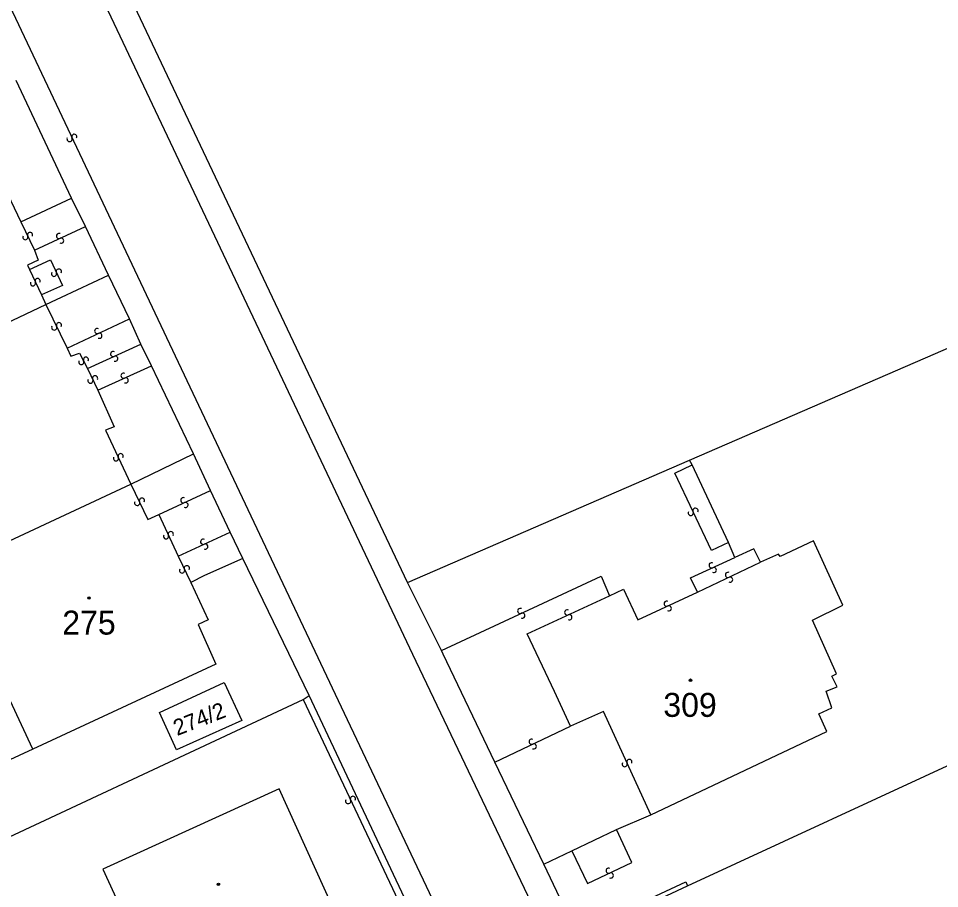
# Model space of a CAD drawing. Extents: x -600391 to -599491, y -1160176 to -1159402.
# Drawn here: x -600122 to -600056.6, y -1159974.1 to -1159912.4 of the extents above; entities that cross this region are included whole.
import ezdxf

# ---------------------------------------------------------------- set-up
doc = ezdxf.new("R2010")
doc.units = 0
for name, color, linetype in [('Level 1', 7, 'Continuous'), ('Level 13', 7, 'Continuous'), ('Level 3', 7, 'Continuous'), ('Level 4', 7, 'Continuous'), ('Level 5', 7, 'Continuous')]:
    doc.layers.add(name, color=color, linetype=linetype)

msp = doc.modelspace()

# ---------------------------------------------------------------- linework, layer by layer
at = {"layer": 'Level 1'}
for points in [[(-600094.36, -1159952.42), (-600122.68, -1159892.59)], [(-600118.2, -1159925.12), (-600122.13, -1159916.77)], [(-600140, -1159926.74), (-600126.12, -1159920.16), (-600124.38, -1159923.72), (-600123.49, -1159923.33), (-600121.81, -1159926.81)], [(-600121.81, -1159926.81), (-600118.2, -1159925.12)], [(-600117.22, -1159927.13), (-600118.2, -1159925.12)], [(-600115.58, -1159930.59), (-600117.22, -1159927.13)], [(-600074.33, -1159943.72), (-600042.25, -1159929.81)], [(-600120.02, -1159932.67), (-600115.58, -1159930.59)], [(-600114.1, -1159933.69), (-600115.58, -1159930.59)], [(-600133.84, -1159939.24), (-600120.02, -1159932.67)], [(-600113.28, -1159935.5), (-600114.1, -1159933.69)], [(-600112.54, -1159937.02), (-600113.28, -1159935.5)], [(-600109.54, -1159943.28), (-600112.54, -1159937.02)], [(-600113.99, -1159945.44), (-600109.54, -1159943.28)], [(-600108.35, -1159945.89), (-600109.54, -1159943.28)], [(-600094.36, -1159952.42), (-600074.33, -1159943.72)], [(-600074.14, -1159944.05), (-600074.33, -1159943.72)], [(-600071.57, -1159949.57), (-600074.14, -1159944.05)], [(-600126.93, -1159951.47), (-600113.99, -1159945.44)], [(-600106.94, -1159948.84), (-600108.35, -1159945.89)], [(-600106.05, -1159950.72), (-600106.94, -1159948.84)], [(-600077.09, -1159968.9), (-600064.59, -1159962.99), (-600065.15, -1159961.74), (-600064.24, -1159961.32), (-600064.64, -1159960.12), (-600063.86, -1159959.81), (-600064.24, -1159959.05), (-600063.9, -1159958.89), (-600065.6, -1159955.09), (-600063.45, -1159954.03), (-600065.53, -1159949.46), (-600067.89, -1159950.56), (-600068.01, -1159950.39), (-600069.3, -1159950.97)], [(-600071.12, -1159950.63), (-600071.57, -1159949.57)], [(-600069.3, -1159950.97), (-600069.76, -1159950.02), (-600071.12, -1159950.63)], [(-600106.05, -1159950.72), (-600108.77, -1159951.91), (-600109.74, -1159952.41)], [(-600101.33, -1159960.44), (-600106.05, -1159950.72)], [(-600109.74, -1159952.41), (-600108.5, -1159955.06), (-600109.21, -1159955.4), (-600107.97, -1159958.22), (-600120.95, -1159964.25)], [(-600091.95, -1159957.24), (-600094.36, -1159952.42)], [(-600088.16, -1159965.16), (-600091.82, -1159957.5), (-600091.95, -1159957.24)], [(-600111.97, -1159961.64), (-600107.37, -1159959.52), (-600106.11, -1159962.22), (-600110.75, -1159964.28), (-600111.97, -1159961.64)], [(-600128.5, -1159973.22), (-600101.77, -1159960.71)], [(-600101.77, -1159960.71), (-600101.33, -1159960.44)], [(-600094.57, -1159974.8), (-600101.33, -1159960.44)], [(-600120.95, -1159964.25), (-600122.9, -1159965.14)], [(-600074.48, -1159973.95), (-600054.19, -1159964.58)], [(-600084.68, -1159972.4), (-600088.16, -1159965.16)], [(-600099.02, -1159976.87), (-600103.46, -1159967.07), (-600115.98, -1159972.77), (-600114.51, -1159975.96)], [(-600079.51, -1159969.95), (-600077.09, -1159968.9)], [(-600082.69, -1159971.45), (-600079.51, -1159969.95)], [(-600084.68, -1159972.4), (-600082.69, -1159971.45)], [(-600082.35, -1159977.29), (-600084.68, -1159972.4)], [(-600082.21, -1159977.57), (-600074.48, -1159973.95)]]:
    msp.add_lwpolyline(points, dxfattribs=at)
at = {"layer": 'Level 13'}
for centre, start, end in [((-600118.347, -1159920.928), 152.47421, 25.06421), ((-600118.013, -1159920.773), 332.68866, 204.78666), ((-600121.153, -1159927.741), 333.36484, 205.46284), ((-600119.097, -1159927.812), 62.4591, 294.55709), ((-600121.486, -1159927.9), 153.15039, 25.74039), ((-600118.943, -1159928.147), 242.24464, 114.83464), ((-600119.112, -1159930.344), 332.16762, 204.26561), ((-600120.613, -1159931.012), 332.89852, 204.99652), ((-600119.447, -1159930.496), 151.95316, 24.54316), ((-600120.946, -1159931.169), 152.68406, 25.27406), ((-600119.436, -1159934.309), 152.90699, 25.49699), ((-600119.103, -1159934.151), 333.12145, 205.21945), ((-600116.387, -1159934.563), 62.67989, 294.77789), ((-600116.232, -1159934.897), 242.46544, 115.05544), ((-600115.255, -1159936.192), 61.90774, 294.00574), ((-600117.514, -1159936.763), 154.13851, 26.72851), ((-600117.185, -1159936.598), 334.35296, 206.45096), ((-600115.104, -1159936.528), 241.69329, 114.28329), ((-600116.866, -1159938.079), 152.82347, 25.41347), ((-600116.533, -1159937.922), 333.03793, 205.13592), ((-600114.516, -1159937.732), 62.15746, 294.25546), ((-600114.364, -1159938.067), 241.94301, 114.53301), ((-600114.722, -1159943.443), 332.43035, 204.52835), ((-600115.057, -1159943.597), 152.21589, 24.80589), ((-600113.546, -1159946.76), 153.07543, 25.66543), ((-600113.213, -1159946.601), 333.28988, 205.38788), ((-600110.266, -1159946.572), 62.09835, 294.19635), ((-600110.114, -1159946.908), 241.8839, 114.4739), ((-600073.913, -1159947.322), 332.41947, 205.00947), ((-600074.248, -1159947.477), 152.63392, 24.73192), ((-600111.497, -1159949.137), 152.15398, 24.74398), ((-600111.162, -1159948.984), 332.36843, 204.46643), ((-600108.865, -1159949.522), 62.0496, 294.14759), ((-600108.714, -1159949.858), 241.83514, 114.42514), ((-600110.023, -1159951.402), 333.07348, 205.17147), ((-600072.766, -1159951.192), 62.15944, 294.25744), ((-600110.356, -1159951.559), 152.85902, 25.44902), ((-600072.614, -1159951.527), 241.94499, 114.53499), ((-600071.608, -1159951.873), 62.90087, 294.99887), ((-600071.451, -1159952.206), 242.68641, 115.27641), ((-600075.956, -1159953.912), 62.18214, 294.28014), ((-600086.356, -1159954.432), 62.33982, 294.43782), ((-600083.016, -1159954.542), 62.22262, 294.32061), ((-600075.804, -1159954.247), 241.96769, 114.55769), ((-600086.203, -1159954.767), 242.12536, 114.71536), ((-600082.863, -1159954.877), 242.00816, 114.59816), ((-600085.547, -1159963.713), 62.73264, 294.83064), ((-600085.392, -1159964.047), 242.51819, 115.10819), ((-600078.602, -1159965.154), 331.75496, 204.34496), ((-600078.938, -1159965.305), 151.96941, 24.06741), ((-600098.233, -1159967.773), 332.67232, 204.77032), ((-600098.567, -1159967.928), 152.45787, 25.04787), ((-600080.077, -1159972.872), 62.609, 294.70699), ((-600079.922, -1159973.207), 242.39454, 114.98454)]:
    msp.add_arc(centre, 0.184, start, end, dxfattribs=at)
at = {"layer": 'Level 3'}
for points in [[(-600058.2, -1160028.15), (-600058.36, -1160028.15), (-600059, -1160028.11), (-600059.48, -1160028.02), (-600059.94, -1160027.88), (-600060.54, -1160027.6), (-600093.98, -1159957.52), (-600113.29, -1159916.73), (-600151.13, -1159836.81), (-600151.44, -1159835.9), (-600151.54, -1159834.48), (-600151.24, -1159833.05), (-600151, -1159832.5)], [(-600159.66, -1159837.59), (-600159.21, -1159837.71), (-600158.35, -1159838.08), (-600157.61, -1159838.58), (-600157.12, -1159839.07), (-600156.56, -1159839.81), (-600136.86, -1159881.35), (-600099.49, -1159960.35), (-600082.51, -1159996.2), (-600082.35, -1159996.48), (-600082.21, -1159996.87), (-600082.15, -1159997.28), (-600082.21, -1159997.74), (-600082.31, -1159998.06), (-600082.48, -1159998.38), (-600082.79, -1159998.74), (-600083.08, -1159998.96), (-600083.18, -1159999.01)], [(-600121.81, -1159926.81), (-600120.83, -1159928.82)], [(-600120.83, -1159928.82), (-600117.22, -1159927.13)], [(-600120.83, -1159928.82), (-600120.57, -1159929.54), (-600121.33, -1159929.88), (-600121.2, -1159930.2)], [(-600121.2, -1159930.2), (-600119.71, -1159929.5), (-600118.86, -1159931.34), (-600120.35, -1159931.98)], [(-600121.2, -1159930.2), (-600120.35, -1159931.98)], [(-600120.35, -1159931.98), (-600120.02, -1159932.67)], [(-600120.02, -1159932.67), (-600118.52, -1159935.78)], [(-600118.52, -1159935.78), (-600114.1, -1159933.69)], [(-600117.07, -1159937.23), (-600113.28, -1159935.5)], [(-600118.52, -1159935.78), (-600118.25, -1159936.35), (-600117.63, -1159936.13), (-600117.07, -1159937.23)], [(-600117.07, -1159937.23), (-600116.33, -1159938.77)], [(-600116.33, -1159938.77), (-600112.54, -1159937.02)], [(-600116.33, -1159938.77), (-600115.19, -1159941.35), (-600115.79, -1159941.59), (-600113.99, -1159945.44)], [(-600071.57, -1159949.57), (-600072.78, -1159950.15), (-600075.38, -1159944.64), (-600074.14, -1159944.05)], [(-600113.99, -1159945.44), (-600112.78, -1159947.93), (-600112.02, -1159947.58)], [(-600112.02, -1159947.58), (-600108.35, -1159945.89)], [(-600112.02, -1159947.58), (-600110.64, -1159950.54)], [(-600110.64, -1159950.54), (-600106.94, -1159948.84)], [(-600110.64, -1159950.54), (-600109.74, -1159952.41)], [(-600073.76, -1159953.1), (-600074.26, -1159952.08), (-600071.12, -1159950.63)], [(-600073.76, -1159953.1), (-600069.3, -1159950.97)], [(-600120.95, -1159964.25), (-600126.77, -1159951.79)], [(-600091.95, -1159957.24), (-600080.61, -1159951.96), (-600080.02, -1159953.36)], [(-600080.02, -1159953.36), (-600079.02, -1159952.89), (-600078, -1159955.06), (-600073.76, -1159953.1)], [(-600082.78, -1159962.61), (-600083.93, -1159960.14), (-600085.85, -1159956.06), (-600080.02, -1159953.36)], [(-600101.77, -1159960.71), (-600095.02, -1159974.99)], [(-600077.09, -1159968.9), (-600080.45, -1159961.56), (-600082.78, -1159962.61)], [(-600088.16, -1159965.16), (-600082.78, -1159962.61)], [(-600082.69, -1159971.45), (-600081.57, -1159973.78), (-600078.43, -1159972.3), (-600079.51, -1159969.95)], [(-600082.35, -1159977.29), (-600074.6, -1159973.66), (-600074.48, -1159973.95)]]:
    msp.add_lwpolyline(points, dxfattribs=at)
at = {"layer": 'Level 5'}
for centre, radius in [((-600116.97, -1159953.51), 0.09), ((-600116.97, -1159953.51), 0.0521), ((-600074.27, -1159959.35), 0.09), ((-600074.27, -1159959.35), 0.0521), ((-600107.78, -1159973.84), 0.09), ((-600107.78, -1159973.84), 0.0521)]:
    msp.add_circle(centre, radius, dxfattribs=at)

# ---------------------------------------------------------------- texts
at = {"layer": 'Level 4'}
for s, p in [('275', (-600118.865, -1159956.11)), ('309', (-600076.195, -1159961.95))]:
    msp.add_text(s, height=1.7, dxfattribs=at).set_placement(p)
msp.add_text('274/2', height=1.14, rotation=21.1986, dxfattribs=at).set_placement((-600110.712, -1159963.313))

doc.saveas('drawing.dxf')
